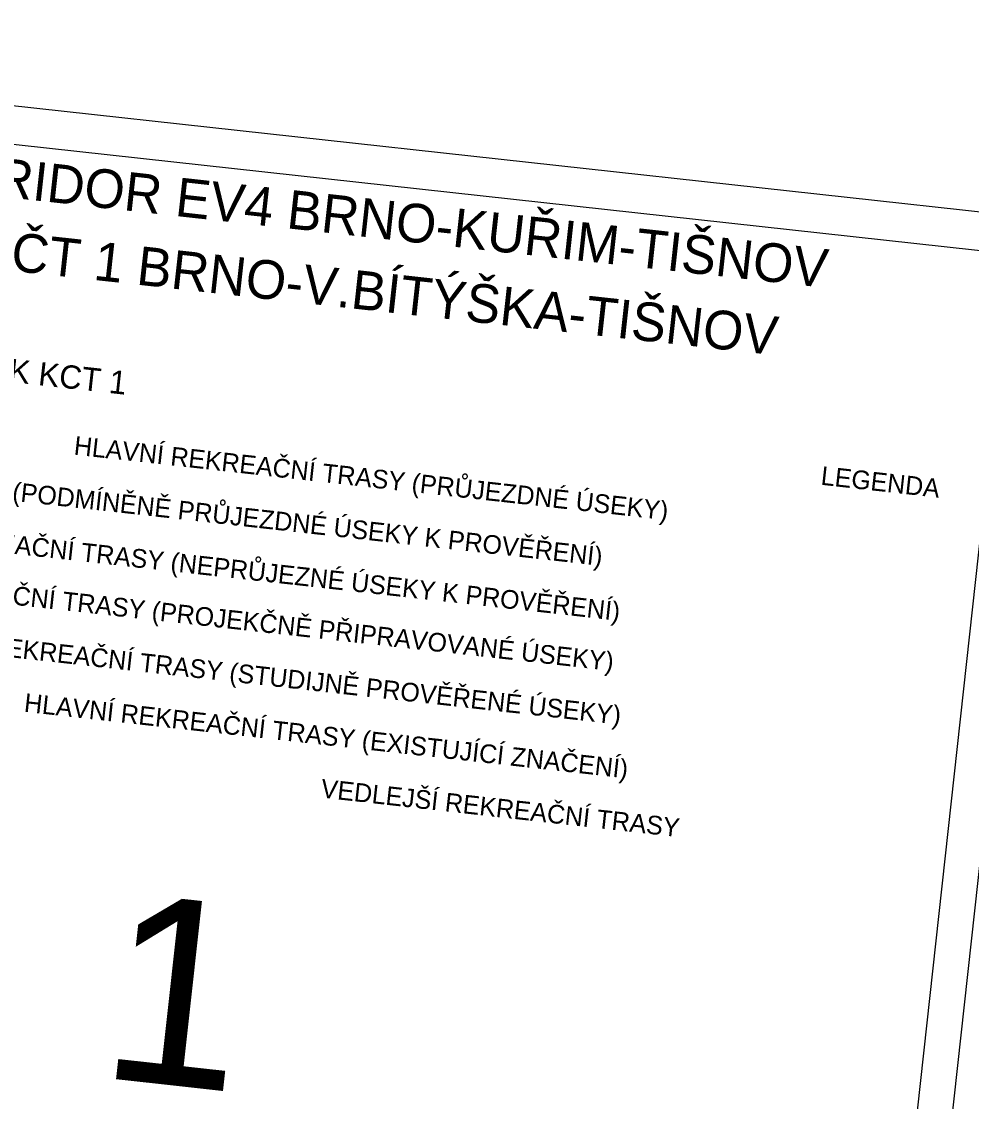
# Model space of a CAD drawing. Extents: x -678204 to -526855, y -1228851 to -1110393.
# Drawn here: x -607858 to -595642, y -1142888 to -1128993 of the extents above; entities that cross this region are included whole.
import ezdxf

# ---------------------------------------------------------------- set-up
doc = ezdxf.new("R2010")
doc.units = 0
for name, color, linetype in [('00_n_cyklo popisy', 7, 'Continuous'), ('00_n_legenda popisy', 7, 'Continuous'), ('00_n_legenda popisy_hlavni', 7, 'Continuous'), ('_HELP BIG', 7, 'Continuous')]:
    doc.layers.add(name, color=color, linetype=linetype)

msp = doc.modelspace()

# ---------------------------------------------------------------- linework, layer by layer
at = {"layer": '_HELP BIG'}
for points in [[(-580037, -1133644), (-608324, -1130538), (-606112, -1110393), (-577825, -1113499)], [(-617877, -1157615), (-614771, -1129327), (-594626, -1131539), (-597732, -1159827)], [(-598180, -1159809), (-595074, -1131522), (-574929, -1133734), (-578035, -1162021)]]:
    msp.add_lwpolyline(points, close=True, dxfattribs=at)

# ---------------------------------------------------------------- texts
at = {"layer": '00_n_cyklo popisy'}
msp.add_text('KORIDOR JMK KCT 1', height=300, rotation=353.6836, dxfattribs=at).set_placement((-610533, -1133351))
at = {"layer": '00_n_legenda popisy'}
for s, p in [('HLAVNÍ REKREAČNÍ TRASY (PRŮJEZDNÉ ÚSEKY) ', (-607193, -1134564)), ('HLAVNÍ REKREAČNÍ TRASY (PODMÍNĚNĚ PRŮJEZDNÉ ÚSEKY K PROVĚŘENÍ) ', (-612328, -1134677)), ('LEGENDA', (-597586, -1134952)), ('HLAVNÍ REKREAČNÍ TRASY (NEPRŮJEZNÉ ÚSEKY K PROVĚŘENÍ) ', (-610294, -1135584)), ('HLAVNÍ REKREAČNÍ TRASY (PROJEKČNĚ PŘIPRAVOVANÉ ÚSEKY) ', (-610536, -1136212)), ('HLAVNÍ REKREAČNÍ TRASY (STUDIJNĚ PROVĚŘENÉ ÚSEKY) ', (-609538, -1137003)), ('HLAVNÍ REKREAČNÍ TRASY (EXISTUJÍCÍ ZNAČENÍ) ', (-607834, -1137873)), ('VEDLEJŠÍ REKREAČNÍ TRASY ', (-604018, -1138977))]:
    msp.add_text(s, height=240, rotation=353.6836, dxfattribs=at).set_placement(p)
at = {"layer": '00_n_legenda popisy_hlavni'}
for s, p in [('KORIDOR EV4 BRNO-KUŘIM-TIŠNOV', (-609167, -1131130)), ('KORIDOR KČT 1 BRNO-V.BÍTÝŠKA-TIŠNOV', (-611722, -1131786))]:
    msp.add_text(s, height=497.66, rotation=353.6836, dxfattribs=at).set_placement(p)
at = {"layer": '_HELP BIG'}
msp.add_text('1', height=2400, rotation=353.6836, dxfattribs=at).set_placement((-606886, -1142575))

doc.saveas('drawing.dxf')
